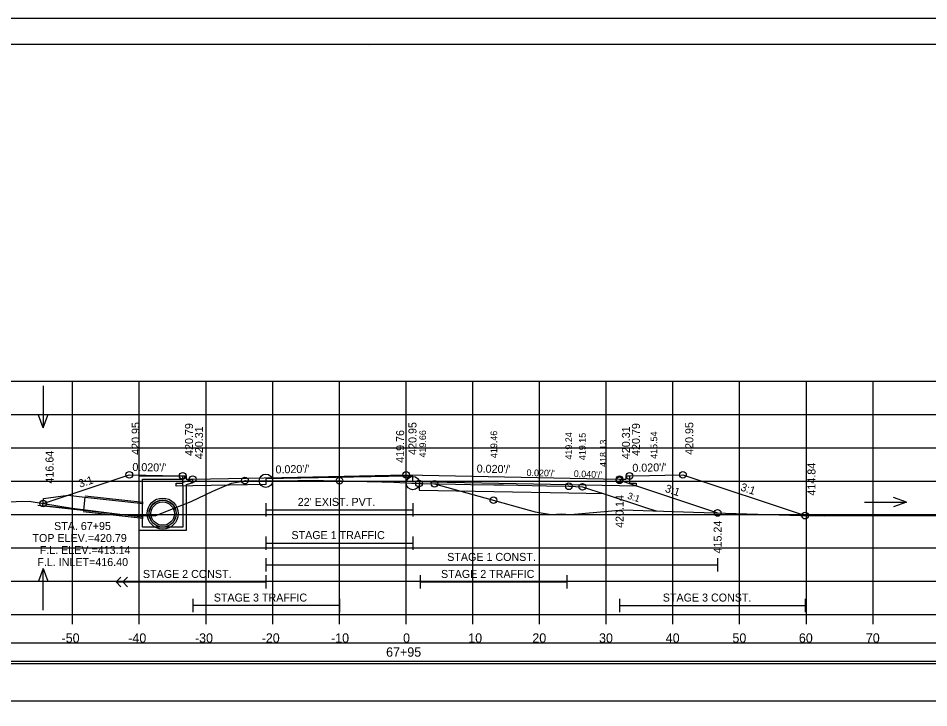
# Model space of a CAD drawing. Extents: x 1371057 to 1372761, y 380005 to 390517.
# Drawn here: x 1371502.7 to 1371639.2, y 385875.2 to 385978.5 of the extents above; entities that cross this region are included whole.
import ezdxf

# ---------------------------------------------------------------- set-up
doc = ezdxf.new("R2010")
doc.units = 0
for name, color, linetype in [('R_Alt Surface', 7, 'Continuous'), ('R_Axis', 7, 'Continuous'), ('R_Axis Annot', 7, 'Continuous'), ('R_Border', 7, 'Continuous'), ('R_Detour', 7, 'Continuous'), ('R_Draft', 7, 'Continuous'), ('R_Exist Surface', 7, 'Continuous'), ('R_Fin Surface', 7, 'Continuous'), ('R_Fin Surface Annot', 7, 'Continuous'), ('R_Grid', 7, 'Continuous'), ('R_No Plot', 7, 'Continuous'), ('R_Striping', 7, 'Continuous'), ('R_Water', 7, 'Continuous'), ('R_Water Annot', 7, 'Continuous'), ('R_Xsect Elev', 7, 'Continuous'), ('R_Xsect Slope', 7, 'Continuous')]:
    doc.layers.add(name, color=color, linetype=linetype)

msp = doc.modelspace()

# ---------------------------------------------------------------- linework, layer by layer
at = {"layer": 'R_Alt Surface'}
for points in [[(1371594.37, 385909.97), (1371594.37, 385908.89), (1371595.37, 385908.87), (1371595.37, 385908.44), (1371592.87, 385908.49), (1371561.89, 385909.11), (1371561.89, 385909.94), (1371560.87, 385909.96), (1371539.85, 385909.54), (1371539.84, 385908.71), (1371528.87, 385908.49), (1371526.37, 385908.44), (1371526.37, 385908.87), (1371527.37, 385908.89), (1371527.37, 385909.97)], [(1371594.37, 385909.97), (1371594.37, 385908.89), (1371595.37, 385908.87), (1371595.37, 385908.44), (1371592.87, 385908.49), (1371561.89, 385909.11), (1371561.89, 385909.94), (1371560.87, 385909.96), (1371539.85, 385909.54), (1371539.84, 385908.71), (1371528.87, 385908.49), (1371526.37, 385908.44), (1371526.37, 385908.87), (1371527.37, 385908.89), (1371527.37, 385909.97)], [(1371539.85, 385905.88), (1371539.85, 385903.88)], [(1371561.89, 385905.88), (1371561.89, 385903.88)], [(1371539.85, 385904.88), (1371561.89, 385904.88)]]:
    msp.add_lwpolyline(points, dxfattribs=at)
at = {"layer": 'R_Axis'}
for p, q in [((1371410.87, 385889.19), (1371710.87, 385889.19)), ((1371510.87, 385887.79), (1371510.87, 385889.19)), ((1371520.87, 385887.79), (1371520.87, 385889.19)), ((1371530.87, 385887.79), (1371530.87, 385889.19)), ((1371540.87, 385887.79), (1371540.87, 385889.19)), ((1371550.87, 385887.79), (1371550.87, 385889.19)), ((1371560.87, 385887.79), (1371560.87, 385889.19)), ((1371570.87, 385887.79), (1371570.87, 385889.19)), ((1371580.87, 385887.79), (1371580.87, 385889.19)), ((1371590.87, 385887.79), (1371590.87, 385889.19)), ((1371600.87, 385887.79), (1371600.87, 385889.19)), ((1371610.87, 385887.79), (1371610.87, 385889.19)), ((1371620.87, 385887.79), (1371620.87, 385889.19)), ((1371630.87, 385887.79), (1371630.87, 385889.19))]:
    msp.add_line(p, q, dxfattribs=at)
at = {"layer": 'R_Border'}
for p, q in [((1371402.87, 385974.65), (1371719.05, 385974.65)), ((1371555.39, 385974.39), (1371555.39, 385974.39)), ((1371555.39, 385974.39), (1371555.39, 385974.39))]:
    msp.add_line(p, q, dxfattribs=at)
at = {"layer": 'R_Detour'}
for points in [[(1371562.8, 385908.87), (1371562.8, 385908.85), (1371562.8, 385908.85), (1371568.27, 385908.74), (1371570.54, 385908.7), (1371574.02, 385908.65), (1371575.48, 385908.62), (1371581.93, 385908.49), (1371585.25, 385908.42), (1371586.27, 385908.38), (1371587.29, 385908.34), (1371588.52, 385907.94), (1371590.42, 385907.32), (1371596.76, 385905.24), (1371597.21, 385905.1), (1371598.35, 385904.72)], [(1371562.8, 385908.85), (1371562.8, 385907.85), (1371562.8, 385907.85), (1371574.02, 385907.65), (1371585.25, 385907.42), (1371590.42, 385907.32)]]:
    msp.add_lwpolyline(points, dxfattribs=at)
msp.add_lwpolyline([(1371407.72, 385882.23), (1371714.03, 385882.23), (1371714.03, 385884.94), (1371407.72, 385884.94)], close=True, dxfattribs=at)
at = {"layer": 'R_Draft'}
msp.add_lwpolyline([(1371407.64, 385876.3), (1371713.95, 385876.3), (1371713.95, 385881.82), (1371407.64, 385881.82)], close=True, dxfattribs=at)
at = {"layer": 'R_Exist Surface'}
msp.add_lwpolyline([(1371498.44, 385906.05), (1371504.36, 385906.17), (1371510.8, 385905.12), (1371518.73, 385904.16), (1371521.14, 385904.02), (1371522.08, 385904.02), (1371523.25, 385903.98), (1371526.1, 385905.12), (1371528.66, 385906.14), (1371531.87, 385907.68), (1371534.7, 385908.9), (1371536.67, 385909.26), (1371536.71, 385909.27), (1371536.77, 385909.27), (1371539.85, 385909.25), (1371539.85, 385909.25), (1371541.73, 385909.26), (1371544.61, 385909.28), (1371544.93, 385909.29), (1371548.48, 385909.28), (1371550.61, 385909.26), (1371550.61, 385909.26), (1371551.19, 385909.26), (1371555.02, 385909.15), (1371557.21, 385909.09), (1371559.01, 385909.02), (1371561.65, 385908.91), (1371561.89, 385908.9), (1371563.43, 385908.85), (1371565.13, 385908.79), (1371580.2, 385904.59), (1371582.63, 385904.19), (1371584.17, 385904.29), (1371585.52, 385904.17), (1371593.41, 385904.88), (1371603.94, 385904.54), (1371619.97, 385904.03), (1371623.62, 385904), (1371642.88, 385904.03)], dxfattribs=at)
at = {"layer": 'R_Fin Surface'}
msp.add_lwpolyline([(1371506.46, 385905.83), (1371506.46, 385905.83), (1371519.37, 385910.13), (1371524.37, 385910.03), (1371527.37, 385909.97), (1371527.87, 385909.97), (1371527.88, 385909.47), (1371528.46, 385909.48), (1371528.87, 385909.49), (1371542.26, 385909.76), (1371560.87, 385910.13), (1371592.87, 385909.49), (1371592.87, 385909.49), (1371593.87, 385909.47), (1371593.87, 385909.79), (1371593.87, 385909.97), (1371594.37, 385909.97), (1371597.37, 385910.03), (1371599.63, 385910.08), (1371602.37, 385910.13), (1371620.69, 385904.03)], dxfattribs=at)
at = {"layer": 'R_Grid'}
for p, q in [((1371410.87, 385924.19), (1371710.87, 385924.19)), ((1371510.87, 385889.19), (1371510.87, 385924.19)), ((1371520.87, 385889.19), (1371520.87, 385924.19)), ((1371530.87, 385889.19), (1371530.87, 385924.19)), ((1371540.87, 385889.19), (1371540.87, 385924.19)), ((1371550.87, 385889.19), (1371550.87, 385924.19)), ((1371560.87, 385889.19), (1371560.87, 385924.19)), ((1371570.87, 385889.19), (1371570.87, 385924.19)), ((1371580.87, 385889.19), (1371580.87, 385924.19)), ((1371590.87, 385889.19), (1371590.87, 385924.19)), ((1371600.87, 385889.19), (1371600.87, 385924.19)), ((1371610.87, 385889.19), (1371610.87, 385924.19)), ((1371620.87, 385889.19), (1371620.87, 385924.19)), ((1371630.87, 385889.19), (1371630.87, 385924.19)), ((1371410.87, 385919.19), (1371710.87, 385919.19)), ((1371410.87, 385914.19), (1371710.87, 385914.19)), ((1371410.87, 385909.19), (1371710.87, 385909.19)), ((1371410.87, 385904.19), (1371710.87, 385904.19)), ((1371410.87, 385899.19), (1371710.87, 385899.19)), ((1371410.87, 385894.19), (1371710.87, 385894.19)), ((1371410.87, 385889.19), (1371710.87, 385889.19))]:
    msp.add_line(p, q, dxfattribs=at)
at = {"layer": 'R_No Plot'}
for p, q in [((1371390.47, 385978.54), (1371723.8, 385978.54)), ((1371512.73, 385907.01), (1371521.47, 385906.04)), ((1371512.46, 385904.62), (1371521.47, 385903.63))]:
    msp.add_line(p, q, dxfattribs=at)
for points in [[(1371390.46, 385978.54), (1371723.8, 385978.54), (1371723.8, 385765.2), (1371390.46, 385765.2)], [(1371636.79, 385974.65), (1371656.41, 385974.65), (1371656.41, 385964.77), (1371672.52, 385964.77), (1371695.72, 385964.77), (1371695.84, 385936.61), (1371719.05, 385936.61), (1371719.05, 385769.19), (1371402.87, 385769.19), (1371402.87, 385974.65)]]:
    msp.add_lwpolyline(points, close=True, dxfattribs=at)
msp.add_lwpolyline([(1371592.87, 385909.32), (1371607.57, 385904.43)], dxfattribs=at)
for centre, radius in [((1371519.37, 385910.13), 0.5), ((1371527.37, 385909.97), 0.5), ((1371528.87, 385909.49), 0.5), ((1371536.71, 385909.27), 0.5), ((1371539.85, 385909.25), 1), ((1371550.87, 385909.26), 0.5), ((1371560.87, 385910.13), 0.5), ((1371561.89, 385908.9), 1), ((1371592.87, 385909.49), 0.5), ((1371592.87, 385909.32), 0.5), ((1371594.37, 385909.97), 0.5), ((1371602.37, 385910.13), 0.5), ((1371562.8, 385908.85), 0.5), ((1371562.8, 385908.85), 0.5), ((1371565.13, 385908.79), 0.5), ((1371585.25, 385908.42), 0.5), ((1371587.29, 385908.34), 0.5), ((1371506.46, 385905.83), 0.5), ((1371524.37, 385904.32), 2.33), ((1371524.37, 385904.33), 2.04), ((1371573.95, 385906.34), 0.5), ((1371607.57, 385904.43), 0.5), ((1371620.69, 385904.03), 0.5)]:
    msp.add_circle(centre, radius, dxfattribs=at)
at = {"layer": 'R_Striping'}
for p, q in [((1371539.85, 385900.91), (1371539.85, 385898.91)), ((1371561.85, 385900.91), (1371561.85, 385898.91)), ((1371539.85, 385899.91), (1371561.85, 385899.91)), ((1371539.85, 385897.64), (1371539.85, 385895.64)), ((1371607.57, 385897.64), (1371607.57, 385895.64)), ((1371539.85, 385896.64), (1371607.57, 385896.64)), ((1371517.41, 385894.09), (1371518.12, 385894.8)), ((1371518.41, 385894.09), (1371519.12, 385894.8)), ((1371539.85, 385895.09), (1371539.85, 385893.09)), ((1371562.95, 385895.09), (1371562.95, 385893.09)), ((1371584.95, 385895.09), (1371584.95, 385893.09)), ((1371517.41, 385894.09), (1371539.85, 385894.09)), ((1371518.12, 385893.38), (1371517.41, 385894.09)), ((1371519.12, 385893.38), (1371518.41, 385894.09)), ((1371562.95, 385894.09), (1371584.95, 385894.09)), ((1371528.87, 385891.55), (1371528.87, 385889.55)), ((1371550.87, 385890.55), (1371528.87, 385890.55)), ((1371550.87, 385891.55), (1371550.87, 385889.55)), ((1371592.87, 385891.55), (1371592.87, 385889.55)), ((1371592.87, 385890.55), (1371620.69, 385890.55)), ((1371620.69, 385891.55), (1371620.69, 385889.55))]:
    msp.add_line(p, q, dxfattribs=at)
at = {"layer": 'R_Water'}
for p, q in [((1371520.87, 385909.97), (1371527.62, 385909.97)), ((1371520.87, 385908.47), (1371520.87, 385909.97)), ((1371527.7, 385909.81), (1371527.37, 385909.47)), ((1371527.7, 385909.81), (1371527.62, 385909.97)), ((1371521.37, 385908.47), (1371521.37, 385909.47)), ((1371521.37, 385909.47), (1371527.37, 385909.47)), ((1371528.87, 385909.49), (1371527.37, 385908.97)), ((1371527.37, 385908.47), (1371527.37, 385908.97)), ((1371528.87, 385908.96), (1371527.87, 385908.62)), ((1371527.87, 385908.47), (1371527.87, 385908.62)), ((1371505.66, 385905.58), (1371521.47, 385903.84)), ((1371512.7, 385906.81), (1371521.47, 385905.84))]:
    msp.add_line(p, q, dxfattribs=at)
for points in [[(1371527.87, 385908.47), (1371527.87, 385901.82), (1371524.37, 385901.82), (1371520.87, 385901.82), (1371520.87, 385908.47)], [(1371527.37, 385908.47), (1371527.37, 385902.32), (1371524.37, 385902.32), (1371521.37, 385902.32), (1371521.37, 385908.47)], [(1371528.87, 385908.96), (1371528.87, 385909.49)]]:
    msp.add_lwpolyline(points, dxfattribs=at)
msp.add_lwpolyline([(1371512.7, 385906.81), (1371512.48, 385904.82), (1371506.4, 385905.49), (1371506.52, 385906.61), (1371510.22, 385907.08)], close=True, dxfattribs=at)
for centre, radius in [((1371524.37, 385904.32), 2), ((1371524.37, 385904.33), 1.75)]:
    msp.add_circle(centre, radius, dxfattribs=at)
at = {"layer": 'R_Water Annot'}
for p, q in [((1371506.46, 385923.46), (1371506.46, 385917.18)), ((1371506.46, 385917.18), (1371505.76, 385919.1)), ((1371506.46, 385917.18), (1371507.16, 385919.1)), ((1371629.59, 385906.05), (1371635.88, 385906.05)), ((1371635.88, 385906.05), (1371633.95, 385906.75)), ((1371635.88, 385906.05), (1371633.95, 385905.35)), ((1371506.46, 385896.12), (1371505.76, 385894.2)), ((1371506.46, 385889.84), (1371506.46, 385896.12)), ((1371506.46, 385896.12), (1371507.16, 385894.2))]:
    msp.add_line(p, q, dxfattribs=at)
at = {"layer": 'R_Xsect Elev'}
msp.add_line((1371560.87, 385908.94), (1371560.87, 385918.94), dxfattribs=at)

# ---------------------------------------------------------------- texts
at = {"layer": 'R_Axis Annot'}
for s, p in [('-50', (1371509.21, 385884.99)), ('-40', (1371519.21, 385884.99)), ('-30', (1371529.21, 385884.99)), ('-20', (1371539.21, 385884.99)), ('-10', (1371549.61, 385884.99)), ('0', (1371560.41, 385884.99)), ('10', (1371570.18, 385884.99)), ('20', (1371579.79, 385884.99)), ('30', (1371589.79, 385884.99)), ('40', (1371599.79, 385884.99)), ('50', (1371609.79, 385884.99)), ('60', (1371619.75, 385884.99)), ('70', (1371629.79, 385884.99)), ('67+95', (1371557.87, 385882.89))]:
    msp.add_text(s, height=1.4, dxfattribs=at).set_placement(p)
at = {"layer": 'R_Fin Surface Annot'}
for s, rotation, p in [('419.66', 90, (1371563.85, 385912.73)), ('419.46', 90, (1371574.52, 385912.65)), ('415.54', 90, (1371598.51, 385912.53)), ('419.24', 90, (1371585.75, 385912.42)), ('419.15', 90, (1371587.79, 385912.34)), ('418.13', 90, (1371590.92, 385911.32)), ("0.020'/'", 358.8535, (1371578.92, 385909.96)), ("0.040'/'", 357.7326, (1371585.99, 385909.82)), ('3:1', 341.9, (1371593.96, 385906.59))]:
    msp.add_text(s, height=1, rotation=rotation, dxfattribs=at).set_placement(p)
at = {"layer": 'R_No Plot'}
for s, rotation, p in [('3:1', 341.5668, (1371599.59, 385907.61)), ('420.14', 90, (1371593.47, 385902.19)), ('415.24', 90, (1371608.17, 385898.36))]:
    msp.add_text(s, height=1.2, rotation=rotation, dxfattribs=at).set_placement(p)
at = {"layer": 'R_Striping'}
for s, p in [('STAGE 1 TRAFFIC', (1371543.68, 385900.51)), ('STAGE 1 CONST.', (1371567.03, 385897.24)), ('STAGE 2 CONST.', (1371521.41, 385894.69)), ('STAGE 2 TRAFFIC', (1371566.1, 385894.69)), ('STAGE 3 TRAFFIC', (1371532.03, 385891.15)), ('STAGE 3 CONST.', (1371599.35, 385891.15))]:
    msp.add_text(s, height=1.2, dxfattribs=at).set_placement(p)
at = {"layer": 'R_Water'}
msp.add_text("22' EXIST. PVT.", height=1.2, dxfattribs=at).set_placement((1371544.62, 385905.48))
at = {"layer": 'R_Water Annot'}
for s, p in [('STA. 67+95', (1371508.09, 385901.87)), ('TOP ELEV.=420.79', (1371504.85, 385900.07)), ('F.L. ELEV.=413.14', (1371505.94, 385898.27)), ('F.L. INLET=416.40', (1371505.58, 385896.47))]:
    msp.add_text(s, height=1.2, dxfattribs=at).set_placement(p)
at = {"layer": 'R_Xsect Elev'}
for s, p in [('420.95', (1371520.92, 385913.13)), ('420.95', (1371562.42, 385913.13)), ('420.95', (1371603.92, 385913.13)), ('420.79', (1371528.92, 385912.97)), ('420.31', (1371530.42, 385912.49)), ('419.76', (1371560.57, 385911.94)), ('420.31', (1371594.42, 385912.49)), ('420.79', (1371595.92, 385912.97)), ('416.64', (1371508.01, 385908.83)), ('414.84', (1371622.24, 385907.03))]:
    msp.add_text(s, height=1.2, rotation=90, dxfattribs=at).set_placement(p)
at = {"layer": 'R_Xsect Slope'}
for s, rotation, p in [("0.020'/'", 358.8543, (1371519.82, 385910.72)), ("0.020'/'", 1.1458, (1371541.3, 385910.34)), ("0.020'/'", 358.8542, (1371571.44, 385910.48)), ("0.020'/'", 1.1458, (1371594.8, 385910.58)), ('3:1', 18.4356, (1371511.97, 385908.19)), ('3:1', 341.5665, (1371610.9, 385907.82))]:
    msp.add_text(s, height=1.2, rotation=rotation, dxfattribs=at).set_placement(p)

doc.saveas('drawing.dxf')
